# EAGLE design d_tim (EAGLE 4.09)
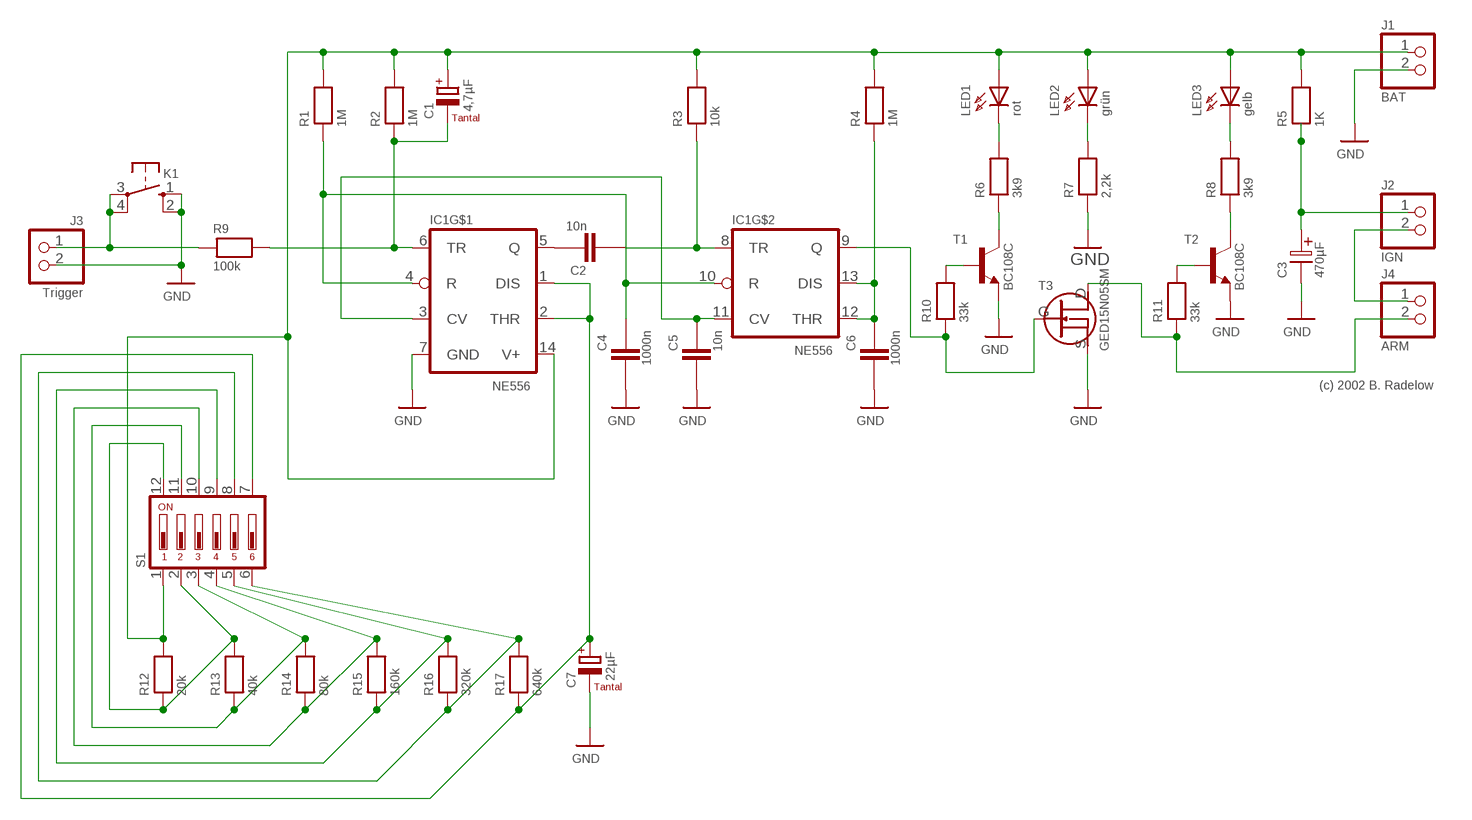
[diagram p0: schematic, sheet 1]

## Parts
C1  4,7µF  TT_4,7  [TT2D5]
C2  10n  MKS2_10N-150N  [C5B2.5]
C3  470µF  EC_470U  [E5-10,5]
C4  1000n  MKS2_1000N  [C5B5]
C5  10n  MKS2_10N-150N  [C5B2.5]
C6  1000n  MKS2_1000N  [C5B5]
C7  22µF  TT_22  [TT2D6]
IC1  NE556  [DIL14]
J1  BAT  PFOSTEN_1X2  [1X02]
J2  IGN  PFOSTEN_1X2  [1X02]
J3  Trigger  PFOSTEN_1X2  [1X02]
J4  ARM  PFOSTEN_1X2  [1X02]
K1  TASTER_OMRON  [B3F-10XX]
LED1  rot  LED_3MM  [LED3MM]
LED2  grün  LED_3MM  [LED3MM]
LED3  gelb  LED_3MM  [LED3MM]
R1  1M  R7,5  [0207/7]
R2  1M  R7,5  [0207/7]
R3  10k  R7,5  [0207/7]
R4  1M  R7,5  [0207/7]
R5  1K  R7,5  [0207/7]
R6  3k9  R7,5  [0207/7]
R7  2,2k  R7,5  [0207/7]
R8  3k9  R7,5  [0207/7]
R9  100k  R7,5  [0207/7]
R10  33k  R7,5  [0207/7]
R11  33k  R7,5  [0207/7]
R12  20k  R7,5  [0207/7]
R13  40k  R7,5  [0207/7]
R14  80k  R7,5  [0207/7]
R15  160k  R7,5  [0207/7]
R16  320k  R7,5  [0207/7]
R17  640k  R7,5  [0207/7]
S1  DIP-SWITCH_6  [DIP06YL]
T1  BC108C  2N2222  [TO18]
T2  BC108C  2N2222  [TO18]
T3  GED15N05SM  [TO252]

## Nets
GND: C3.- C4.2 C5.2 C6.2 C7.- IC1.7(GND) J1.2 J3.2 K1.1(S) K1.2(S1) R7.1 T1.1(E) T2.1(E) T3.S
N$1: J2.2 J4.1
N$2: LED2.K(C) R7.2
N$3: LED1.K(C) R6.2
N$4: LED3.K(C) R8.2
N$5: IC1.9(Q) R10.1 T3.G
N$6: R10.2 T1.2(B)
N$7: C5.1 IC1.3(CV) IC1.11(CV)
N$8: J4.2 R11.1 T3.D
N$9: C4.1 IC1.4(R) IC1.10(R) R1.1
N$10: C7.+ IC1.1(DIS) IC1.2(THR) R17.1 S1.7
N$11: C3.+ J2.1 R5.1
N$12: C6.1 IC1.12(THR) IC1.13(DIS) R4.1
N$13: R12.1 R13.2 S1.2 S1.12
N$14: R13.1 R14.2 S1.3 S1.11
N$15: R14.1 R15.2 S1.4 S1.10
N$16: R15.1 R16.2 S1.5 S1.9
N$17: R6.1 T1.3(C)
N$18: R16.1 R17.2 S1.6 S1.8
N$19: C2.2 IC1.8(TR) R3.1
N$20: C1.- IC1.6(TR) R2.1 R9.2
N$21: J3.1 K1.3(P) K1.4(P1) R9.1
N$22: C2.1 IC1.5(Q)
N$25: R8.1 T2.3(C)
N$27: R11.2 T2.2(B)
V+: C1.+ IC1.14(V+) J1.1 LED1.A LED2.A LED3.A R1.2 R2.2 R3.2 R4.2 R5.2 R12.2 S1.1

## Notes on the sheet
- (c) 2002 B. Radelow

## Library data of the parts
C1 = _d_serie:TT_4,7: Tantal-EC 4,7µF
C2 C5 = _d_serie:MKS2_10N-150N: WIMA MKS2 Folienkondensator
C3 = _d_serie:EC_470U: 470µF 16V, Höhe 17mm
C4 C6 = _d_serie:MKS2_1000N: WIMA MKS2 Folienkondensator 1µF
C7 = _d_serie:TT_22: Tantal-EC 22µF
IC1 = _d_serie:NE556: Dual Timer
J1-J4 = _d_serie:PFOSTEN_1X2: Pfosten 2x1
K1 = _d_serie:TASTER_OMRON: Taster, Omron
LED1-LED3 = _d_serie:LED_3MM
R1-R17 = _d_serie:R7,5: Widerstand 0,3 Watt liegend
S1 = _d_serie:DIP-SWITCH_6: DIP-Switch 6-fach
T1 T2 = _d_serie:2N2222
T3 = _d_serie:GED15N05SM: N-Channel Power-FET

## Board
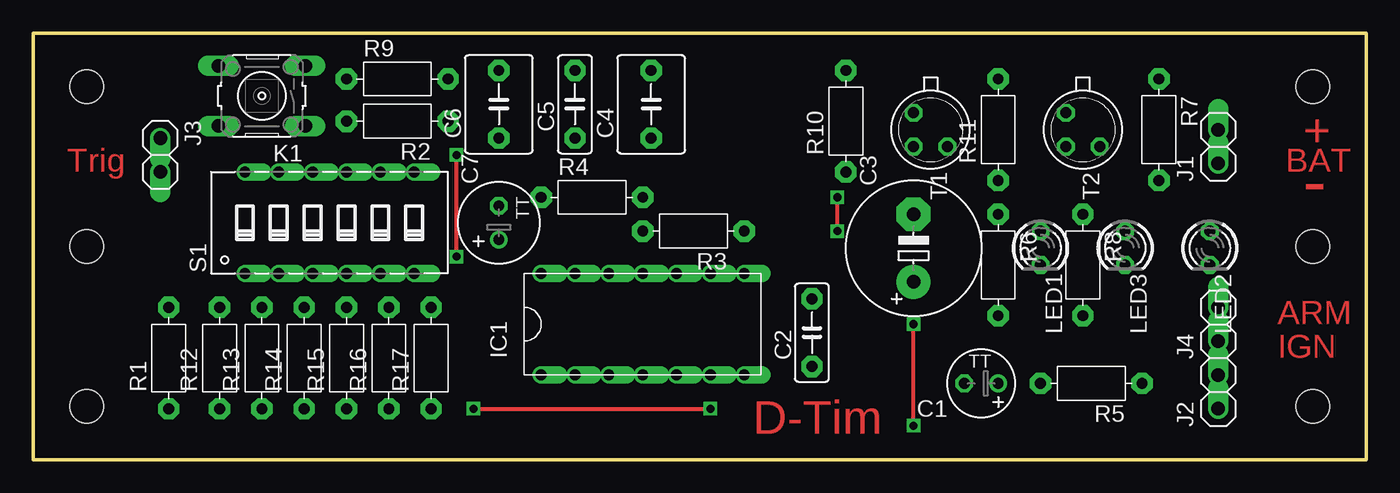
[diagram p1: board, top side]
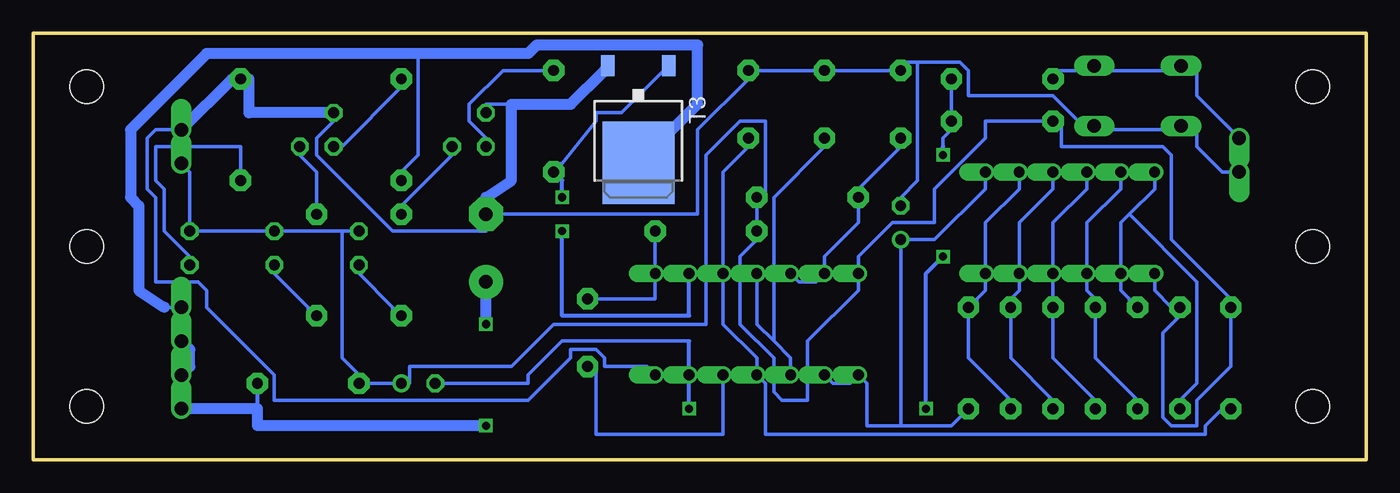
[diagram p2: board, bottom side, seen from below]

Size 100 x 32 mm. Coordinates in mm from the lower left corner, seen from the top.
Outline: 0,0 0,32 100,32 100,0 0,0
Copper layers used: Top, Bottom
Holes 2.54 mm at 4,4 4,28 4,16 96,16 96,4 96,28
tRestrict: area 0,-1.3 to 101.6,33
bRestrict: area 92,24 to 100,32; area 92,0 to 100,8; area 92,12 to 100,20; area 0,0 to 8,8; area 0,24 to 8,32; area 0,12 to 8,20

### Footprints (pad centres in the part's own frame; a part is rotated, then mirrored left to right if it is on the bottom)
TT2D5 = drill 0.813 round: + -1.27,0 | drill 0.813 octagon: - 1.27,0
C5B2.5 = drill 0.813 pad 1.6 octagon: 1 -2.54,0; 2 2.54,0
E5-10,5 = drill 1.016 pad 2.54 round: + -2.54,0 | drill 1.016 pad 2.54 octagon: - 2.54,0
C5B5 = drill 0.813 pad 1.6 octagon: 1 -2.54,0; 2 2.54,0
TT2D6 = drill 0.813 round: + -1.27,0 | drill 0.813 octagon: - 1.27,0
DIL14 = drill 0.813 offset: 1 -7.62,-3.81; 2 -5.08,-3.81; 3 -2.54,-3.81; 4 0,-3.81; 5 2.54,-3.81; 6 5.08,-3.81; 7 7.62,-3.81; 8 7.62,3.81; 9 5.08,3.81; 10 2.54,3.81; 11 0,3.81; 12 -2.54,3.81; 13 -5.08,3.81; 14 -7.62,3.81
1X02 = drill 1.016 offset: 1 -1.27,0; 2 1.27,0
B3F-10XX = drill 1.016 long: 1 -3.251,2.261; 2 3.251,2.261; 3 -3.251,-2.261; 4 3.251,-2.261
LED3MM = drill 0.813 octagon: A -1.27,0; K 1.27,0
0207/7 = drill 0.813 pad 1.6 octagon: 1 -3.81,0; 2 3.81,0
DIP06YL = drill 0.813 offset: 1 -6.35,-3.81; 2 -3.81,-3.81; 3 -1.27,-3.81; 4 1.27,-3.81; 5 3.81,-3.81; 6 6.35,-3.81; 7 6.35,3.81; 8 3.81,3.81; 9 1.27,3.81; 10 -1.27,3.81; 11 -3.81,3.81; 12 -6.35,3.81
TO18 = drill 0.813 octagon: 1 -1.27,-1.27; 2 1.27,-1.27; 3 1.27,1.27
TO252 = smd 5.4 x 6.2: D 0,1.23 | smd 1 x 1.6: G -2.28,-6.07; S 2.28,-6.07

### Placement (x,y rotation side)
C1  71.12,5.71 180 top
C2  58.42,9.53 90 top
C3  66.04,15.88 90 top
C4  46.35,26.67 90 top
C5  40.64,26.67 90 top
C6  34.92,26.67 90 top
C7  34.92,17.78 90 top
IC1  45.72,10.16 0 top
J1  88.9,23.5 90 top
J2  88.9,5.08 90 top
J3  9.53,22.86 270 top
J4  88.9,10.16 90 top
K1  17.14,27.3 180 top
LED1  75.56,15.88 270 top
LED2  88.27,15.88 270 top
LED3  81.92,15.88 270 top
R1  10.16,7.62 90 top
R2  27.3,25.4 180 top
R3  49.53,17.14 180 top
R4  41.91,19.68 0 top
R5  79.38,5.71 180 top
R6  72.39,14.61 270 top
R7  84.45,24.77 270 top
R8  78.74,14.61 270 top
R9  27.3,28.57 0 top
R10  60.96,25.4 90 top
R11  72.39,24.77 90 top
R12  13.97,7.62 90 top
R13  17.14,7.62 90 top
R14  20.32,7.62 90 top
R15  23.5,7.62 90 top
R16  26.67,7.62 90 top
R17  29.84,7.62 90 top
S1  22.23,17.78 0 top
T1  67.31,24.77 270 top
T2  78.74,24.77 270 top
T3  54.61,23.5 180 bottom

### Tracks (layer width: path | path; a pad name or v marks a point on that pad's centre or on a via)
GND
  Bottom 0.254: 83.82,28.57 R7.1 85.09,28.57 | IC1.7 53.98,6.99 57.15,6.99 57.15,7.62 57.78,8.26 59.69,8.26 59.69,7.62 62.87,4.45 81.92,4.45 81.92,6.35 87,11.43 87,12.7 87.63,13.34 90.81,13.34 90.81,19.68 91.44,20.32 91.44,24.13 90.81,24.77 J1.2 | 64.14,26.67 66.04,26.67 T1.1 | 57.15,29.21 T3.S | 33.66,29.84 34.92,29.84 C6.2 C5.2 C4.2 46.35,28.57 50.16,24.77 50.16,18.41 C3.- 66.04,17.14 73.03,17.14 78.74,22.86 78.74,24.13 77.47,25.4 T2.1 | 33.66,29.84 33.66,20.95 34.92,19.68 C7.- | 33.66,29.84 30.48,29.84 29.84,29.21 29.84,27.3 23.5,27.3 21.59,25.4 K1.1 19.05,24.77 15.24,24.77 K1.2 12.7,24.77 12.7,23.5 10.79,21.59 J3.2
  Bottom 0.813: 83.82,28.57 83.82,26.04 T2.1 | 85.09,28.57 J1.2 | 57.15,29.21 59.69,26.67 64.14,26.67 64.14,20.95 66.04,19.68 C3.-
N$1
  Bottom 0.813: J2.2 88.27,6.99 88.27,8.26 J4.1
N$2
  Bottom 0.254: LED2.K 88.27,15.24 90.17,17.14 90.17,20.32 90.81,20.95 90.81,23.5 84.45,23.5 R7.2
N$3
  Bottom 0.254: LED1.K 75.56,13.97 73.03,11.43 73.03,10.79 R6.2
N$4
  Bottom 0.254: LED3.K 81.92,13.97 79.38,11.43 79.38,10.79 R8.2
N$5  (via drill 0.61)
  Top 0.305: v60.33,17.14 v60.33,19.68
  Bottom 0.254: T3.G 52.7,29.21 55.88,26.04 57.78,26.04 57.78,25.4 60.33,22.23 60.96,22.23 R10.1
  Bottom 0.305: IC1.9 50.8,10.79 60.33,10.79 v60.33,17.14 | v60.33,19.68 60.33,20.95 R10.1
N$6
  Bottom 0.254: T1.2 66.04,24.13 67.31,25.4 67.31,26.67 64.77,29.21 R10.2
N$7
  Bottom 0.254: 44.45,8.89 45.72,10.16 IC1.11 | 44.45,8.89 43.18,7.62 IC1.3 | 44.45,8.89 44.45,19.68 40.64,23.5 C5.1
N$8
  Bottom 0.254: 71.12,30.48 71.12,22.86 72.39,21.59 R11.1 | 90.17,11.43 J4.2
  Bottom 0.305: T3.D 54.57,22.27
  Bottom 0.813: 54.57,22.27 50.16,26.67 50.16,31.11 62.23,31.11 62.87,30.48 71.12,30.48 87,30.48 92.71,24.77 92.71,19.68 92.08,19.05 92.08,12.7 90.17,11.43
N$9
  Bottom 0.254: R1.1 10.79,3.81 12.06,2.54 12.06,1.91 45.09,1.91 45.09,5.71 IC1.4 45.72,7.62 48.26,10.16 IC1.10 48.26,21.59 46.35,23.5 C4.1
N$10
  Bottom 0.254: S1.7 28.57,20.32 32.38,16.51 C7.+ 34.92,2.54 | IC1.2 40.01,5.71 38.73,5.71 IC1.1 37.47,5.71 37.47,2.54 34.92,2.54 | R17.1 31.11,2.54 34.92,2.54
N$11  (via drill 0.61)
  Top 0.305: v66.04,2.54 v66.04,10.16
  Bottom 0.305: 83.19,3.81 R5.1
  Bottom 0.813: v66.04,2.54 83.19,2.54 83.19,3.81 J2.1 | v66.04,10.16 C3.+
N$12
  Bottom 0.254: IC1.12 42.55,13.34 41.27,13.34 IC1.13 40.64,15.24 38.1,17.78 R4.1 38.1,20.32 34.92,23.5 C6.1
N$13
  Bottom 0.254: R13.2 17.78,11.43 17.78,12.06 18.41,12.7 S1.2 18.41,17.78 17.78,18.41 | 17.78,18.41 15.88,20.32 S1.12 | 17.78,18.41 12.7,13.34 12.7,5.71 13.97,4.45 R12.1
N$14
  Bottom 0.254: S1.11 18.41,20.32 20.95,17.78 S1.3 20.95,12.7 20.32,12.06 R14.2 20.32,7.62 17.14,4.45 R13.1
N$15
  Bottom 0.254: S1.10 20.95,20.32 23.5,17.78 S1.4 R15.2 23.5,7.62 20.32,4.45 R14.1
N$16
  Bottom 0.254: S1.9 23.5,20.32 26.04,17.78 S1.5 26.04,12.7 26.67,12.06 R16.2 26.67,7.62 23.5,4.45 R15.1
N$17
  Bottom 0.254: T1.3 68.58,22.86 72.39,19.05 R6.1
N$18
  Bottom 0.254: S1.8 26.04,20.32 28.57,17.78 S1.6 28.57,12.7 29.21,12.06 29.21,11.43 R17.2 29.84,7.62 26.67,4.45 R16.1
N$19
  Bottom 0.254: R3.1 IC1.8 53.34,12.06 C2.2
N$20  (via drill 0.61)
  Top 0.305: v33.02,3.81 v50.8,3.81 | v31.75,15.24 v31.75,22.86
  Bottom 0.254: C1.- 62.87,5.71 62.87,6.35 60.33,8.89 50.8,8.89 IC1.6 | 31.75,23.5 31.75,24.13 31.11,24.77 R2.1 R9.2
  Bottom 0.305: v50.8,3.81 50.8,8.89 | v33.02,3.81 33.02,13.97 v31.75,15.24 | v31.75,22.86 31.75,23.5
N$21
  Bottom 0.254: R9.1 23.5,29.21 21.59,29.21 K1.3 19.05,29.21 15.24,29.21 K1.4 12.7,29.21 12.7,27.3 J3.1
N$22
  Bottom 0.254: IC1.5 48.26,1.91 57.78,1.91 57.78,6.99 C2.1
N$25
  Bottom 0.254: T2.3 80.01,22.86 78.74,21.59 R8.1
N$27
  Bottom 0.254: T2.2 76.83,23.5 72.39,27.94 R11.2
V+
  Bottom 0.254: J1.1 88.27,21.59 LED2.A LED3.A 76.83,17.14 | 76.83,17.14 LED1.A | 76.83,17.14 76.83,7.62 75.56,6.35 R5.2 C1.+ 71.75,5.71 71.75,6.99 64.14,6.99 60.96,10.16 49.53,10.16 49.53,22.86 46.99,25.4 45.09,25.4 45.09,19.68 R4.2 R3.2 45.72,16.51 46.99,15.24 46.99,10.16 44.45,7.62 44.45,5.08 43.81,4.45 41.91,4.45 41.91,8.89 38.1,12.7 IC1.14 38.1,15.24 35.56,17.78 32.38,17.78 32.38,20.32 28.57,24.13 28.57,25.4 R2.2 22.86,25.4 22.86,23.5 15.24,23.5 14.61,22.86 14.61,16.51 10.16,12.06 R1.2 10.16,6.99 12.7,4.45 12.7,2.54 14.61,2.54 15.24,3.17 15.24,9.53 13.97,10.79 R12.2 14.61,11.43 15.88,12.7 S1.1

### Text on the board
Top: + | Trig | BAT | - | ARM | IGN | D-Tim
